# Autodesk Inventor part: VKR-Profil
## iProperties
Created: 2001-12
Part Number: VKR-Profil
Material: Steel, Mild
Description: VKR 75x75x3_375
Document SubType Name: Modeling
Designer: Tobben
Control State: 0
Master: False
Checked Out: False
Shininess: 64.0
Length Units: 11269
Angle Units: 11279
Time Units: 11290
Mass Units: 11283
Length Display Precision: 3
Angle Display Precision: 2
Density: 0.0
Volumn: 0.0
Area: 0.0
PropertySet Name: Model Information
Author: Tobben
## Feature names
1. Extrusion1
